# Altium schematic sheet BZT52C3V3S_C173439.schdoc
size 127 x 101 mm
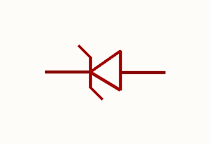
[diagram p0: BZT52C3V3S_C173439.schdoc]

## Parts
D?  bzt52c3v3s_c173439  [SOD-323_L1.8-W1.3-LS2.5-RD]  (value not drawn)

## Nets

Not connected (* = marked no-connect by the designer): D? 1 2

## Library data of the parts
D? = bzt52c3v3s_c173439: 二极管配置:1个独立式;稳压值(标称值):3.3V;稳压值(范围):3.1V~3.5V;耗散功率(Pd):200mW;; Manufacturer: MDD(辰达半导体); AddInBom: yes; ModelId: db63db13d9e342eb939127d413d6200b; ModelTransform: 104.3305,51.181,0,0,0,0,0,-0.004,0; Diode Configuration: 1个独立式; Zener Voltage(Nom): 3.3V; Reverse Leakage Current (Ir): 20uA@1V; Pd - Power Dissipation: 200mW; Impedance(Zzt): 130Ω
